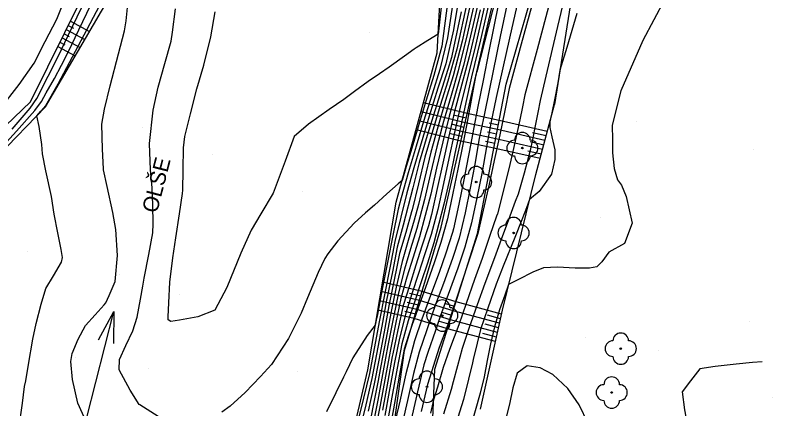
# Model space of a CAD drawing. Extents: x -448957 to -448612, y -1107690 to -1107245.
# Drawn here: x -448666.49 to -448618.03, y -1107372.46 to -1107347.3 of the extents above; entities that cross this region are included whole.
import ezdxf

# ---------------------------------------------------------------- set-up
doc = ezdxf.new("R2010")
doc.units = 0
for name, color, linetype in [('22', 7, 'Continuous'), ('Default', 7, 'Continuous'), ('Vrstva 1', 7, 'Continuous'), ('Vrstva 14', 7, 'Continuous'), ('Vrstva 15', 7, 'Continuous'), ('Vrstva 16', 7, 'Continuous'), ('Vrstva 17', 7, 'Continuous'), ('Vrstva 22', 7, 'Continuous'), ('Vrstva 45', 7, 'Continuous')]:
    doc.layers.add(name, color=color, linetype=linetype)

# ---------------------------------------------------------------- blocks, each defined once
blk = doc.blocks.new('POINT_DISPLAY')
at = {"layer": 'Default'}
blk.add_line((0, 0), (0, 0), dxfattribs=at)
blk = doc.blocks.new('STROM$5')
at = {"layer": '22'}
blk.add_circle((0, 0), 0.5, dxfattribs=at)
for centre, start, end in [((0, 5), 0, 180), ((-5, 0), 90, 270), ((5, 0), 270, 90), ((0, -5), 180, 0)]:
    blk.add_arc(centre, 5, start, end, dxfattribs=at)
blk = doc.blocks.new('TOK')
at = {"layer": 'Default'}
for p, q in [((-5, 50), (0, 70)), ((0, 0), (0, 70)), ((0, 70), (5, 50))]:
    blk.add_line(p, q, dxfattribs=at)

msp = doc.modelspace()

# ---------------------------------------------------------------- linework, layer by layer
at = {"layer": 'Vrstva 14'}
for p, q in [((-448639.5, -1107349.716), (-448638.523, -1107332.119)), ((-448632.378, -1107333.085), (-448636.968, -1107350.917)), ((-448635.081, -1107351.7), (-448629.722, -1107333.044)), ((-448628.814, -1107332.973), (-448631.997, -1107353.013)), ((-448665.508, -1107352.833), (-448661.274, -1107344.294)), ((-448664.543, -1107353.162), (-448659.693, -1107344.838)), ((-448642.118, -1107359.249), (-448639.5, -1107349.716)), ((-448639.238, -1107360.851), (-448636.968, -1107350.917)), ((-448636.914, -1107361.247), (-448635.081, -1107351.7)), ((-448673.407, -1107360.41), (-448665.508, -1107352.833)), ((-448672.108, -1107360.875), (-448664.543, -1107353.162)), ((-448633.189, -1107357.486), (-448631.997, -1107353.013)), ((-448635.327, -1107366.145), (-448633.189, -1107357.486)), ((-448643.941, -1107369.964), (-448642.118, -1107359.249)), ((-448641.584, -1107368.733), (-448639.238, -1107360.851)), ((-448639.643, -1107369.918), (-448636.914, -1107361.247)), ((-448636.736, -1107372.468), (-448635.327, -1107366.145)), ((-448643.143, -1107379.65), (-448641.584, -1107368.733)), ((-448646.084, -1107379.123), (-448643.941, -1107369.964)), ((-448640.133, -1107381.504), (-448639.643, -1107369.918))]:
    msp.add_line(p, q, dxfattribs=at)
at = {"layer": 'Vrstva 15'}
for p, q in [((-448662.953, -1107347.68), (-448661.732, -1107348.338)), ((-448663.22, -1107348.218), (-448662.034, -1107348.856)), ((-448663.086, -1107347.949), (-448662.748, -1107348.131)), ((-448663.486, -1107348.756), (-448662.337, -1107349.375)), ((-448663.353, -1107348.487), (-448663.024, -1107348.664)), ((-448663.753, -1107349.294), (-448662.639, -1107349.894)), ((-448663.62, -1107349.025), (-448663.301, -1107349.196)), ((-448637.58, -1107353.594), (-448640.372, -1107352.892)), ((-448637.713, -1107354.179), (-448640.531, -1107353.47)), ((-448637.646, -1107353.886), (-448638.444, -1107353.686)), ((-448635.527, -1107354.025), (-448637.58, -1107353.594)), ((-448637.847, -1107354.764), (-448640.69, -1107354.049)), ((-448635.641, -1107354.614), (-448637.713, -1107354.179)), ((-448632.454, -1107354.729), (-448635.527, -1107354.025)), ((-448637.981, -1107355.349), (-448640.849, -1107354.628)), ((-448637.78, -1107354.471), (-448638.585, -1107354.269)), ((-448635.584, -1107354.32), (-448636.17, -1107354.196)), ((-448632.609, -1107355.309), (-448635.641, -1107354.615)), ((-448637.914, -1107355.056), (-448638.726, -1107354.852)), ((-448635.754, -1107355.204), (-448637.847, -1107354.764)), ((-448635.697, -1107354.909), (-448636.289, -1107354.785)), ((-448632.531, -1107355.019), (-448633.41, -1107354.818)), ((-448635.867, -1107355.793), (-448637.981, -1107355.349)), ((-448635.81, -1107355.498), (-448636.408, -1107355.373)), ((-448632.763, -1107355.889), (-448635.754, -1107355.204)), ((-448632.686, -1107355.599), (-448633.552, -1107355.4)), ((-448632.918, -1107356.469), (-448635.867, -1107355.794)), ((-448632.841, -1107356.179), (-448633.695, -1107355.983)), ((-448640.461, -1107364.959), (-448642.989, -1107364.37)), ((-448640.632, -1107365.536), (-448643.09, -1107364.963)), ((-448640.547, -1107365.248), (-448641.269, -1107365.079)), ((-448638.291, -1107365.624), (-448640.461, -1107364.959)), ((-448640.804, -1107366.112), (-448643.191, -1107365.555)), ((-448640.718, -1107365.824), (-448641.42, -1107365.66)), ((-448638.472, -1107366.196), (-448640.632, -1107365.535)), ((-448638.382, -1107365.91), (-448639.001, -1107365.72)), ((-448635.385, -1107366.403), (-448638.291, -1107365.624)), ((-448640.975, -1107366.688), (-448643.292, -1107366.148)), ((-448640.89, -1107366.4), (-448641.572, -1107366.241)), ((-448638.652, -1107366.768), (-448640.803, -1107366.11)), ((-448638.562, -1107366.482), (-448639.179, -1107366.293)), ((-448635.515, -1107366.99), (-448638.472, -1107366.196)), ((-448638.832, -1107367.341), (-448640.974, -1107366.685)), ((-448635.646, -1107367.576), (-448638.652, -1107366.769)), ((-448635.45, -1107366.697), (-448636.28, -1107366.474)), ((-448638.742, -1107367.054), (-448639.356, -1107366.866)), ((-448635.581, -1107367.283), (-448636.425, -1107367.056)), ((-448635.776, -1107368.162), (-448638.832, -1107367.342)), ((-448635.711, -1107367.869), (-448636.57, -1107367.638))]:
    msp.add_line(p, q, dxfattribs=at)
at = {"layer": 'Vrstva 16'}
for points in [[(-448634.838, -1107345.644), (-448635.47, -1107348.671), (-448636.153, -1107352.014), (-448636.495, -1107353.684), (-448636.805, -1107355.19), (-448637.098, -1107356.811), (-448637.378, -1107358.347), (-448637.703, -1107359.935), (-448638.09, -1107361.54), (-448638.524, -1107362.847), (-448639.095, -1107364.449), (-448639.602, -1107365.79), (-448640.16, -1107367.4), (-448640.639, -1107368.83), (-448641.002, -1107370.2), (-448641.402, -1107371.934), (-448641.692, -1107373.219)], [(-448667.925, -1107356.375), (-448666.407, -1107354.708), (-448665.235, -1107353.392), (-448664.81, -1107352.82), (-448664.498, -1107352.256), (-448663.978, -1107351.336), (-448663.512, -1107350.501), (-448663.09, -1107349.674), (-448662.412, -1107348.242), (-448661.639, -1107346.632)], [(-448637.968, -1107347.084), (-448638.444, -1107349.382), (-448638.576, -1107349.995), (-448638.808, -1107350.765), (-448639.306, -1107352.324), (-448639.653, -1107353.414), (-448640.127, -1107354.985), (-448640.648, -1107356.709), (-448641.058, -1107358.341), (-448641.677, -1107360.71), (-448642.049, -1107362.132), (-448642.365, -1107363.706), (-448642.728, -1107365.523), (-448643.039, -1107367.169), (-448643.38, -1107368.974), (-448643.679, -1107370.525), (-448644.056, -1107372.192), (-448644.417, -1107373.675)], [(-448636.757, -1107346.965), (-448637.451, -1107349.97), (-448638.385, -1107353.454), (-448638.765, -1107355.113), (-448639.146, -1107356.767), (-448639.496, -1107358.378), (-448639.863, -1107360.04), (-448640.055, -1107360.77), (-448640.473, -1107362.068), (-448640.869, -1107363.283), (-448641.278, -1107364.587), (-448641.672, -1107365.844), (-448642.022, -1107367.406), (-448642.34, -1107368.936), (-448642.378, -1107369.121), (-448642.659, -1107370.692), (-448642.997, -1107372.552)], [(-448630.567, -1107347.19), (-448631.215, -1107349.365), (-448631.647, -1107350.807), (-448631.789, -1107351.62), (-448631.995, -1107352.71), (-448632.173, -1107353.546), (-448632.288, -1107354.106), (-448632.288, -1107354.277), (-448632.286, -1107354.488), (-448632.167, -1107355.066), (-448631.975, -1107355.895), (-448631.967, -1107356.531), (-448632.191, -1107357.455), (-448632.968, -1107358.56), (-448633.585, -1107359.089), (-448633.783, -1107359.608), (-448634.079, -1107360.389), (-448634.538, -1107361.516), (-448635.274, -1107363.342), (-448635.723, -1107364.5), (-448636.263, -1107366.033), (-448636.735, -1107367.397), (-448636.944, -1107368.267), (-448637.194, -1107369.308), (-448637.243, -1107369.512), (-448637.485, -1107370.559), (-448637.809, -1107371.857), (-448638.31, -1107373.42)]]:
    msp.add_lwpolyline(points, dxfattribs=at)
at = {"layer": 'Vrstva 17'}
for points in [[(-448667.516, -1107353.349), (-448666.237, -1107351.73), (-448665.263, -1107350.375), (-448664.557, -1107348.977), (-448663.821, -1107347.557), (-448663.111, -1107345.787), (-448662.585, -1107344.345), (-448662.505, -1107344.114), (-448662.472, -1107343.99), (-448662.32, -1107343.423), (-448662.081, -1107342.57), (-448661.948, -1107342.013), (-448662.027, -1107339.815), (-448662.213, -1107337.02), (-448662.425, -1107335.598), (-448662.903, -1107332.976), (-448663.381, -1107328.546), (-448663.491, -1107325.878), (-448663.429, -1107325.418), (-448662.646, -1107323.333), (-448661.288, -1107320.368), (-448660.143, -1107318.417), (-448659.03, -1107316.692)], [(-448636.52, -1107344.916), (-448637.202, -1107347.896), (-448637.81, -1107350.513), (-448637.828, -1107350.579), (-448638.283, -1107352.159), (-448638.741, -1107353.75), (-448639.135, -1107355.395), (-448639.535, -1107357.086), (-448639.904, -1107358.747), (-448640.621, -1107361.455), (-448641.037, -1107362.755), (-448641.43, -1107364.039), (-448641.829, -1107365.408), (-448642.147, -1107366.943), (-448642.513, -1107368.762), (-448642.803, -1107370.362), (-448643.149, -1107372.226), (-448643.435, -1107373.732)], [(-448637.958, -1107345.243), (-448638.463, -1107348.227), (-448638.95, -1107350.404), (-448639.446, -1107351.964), (-448640.008, -1107353.756), (-448640.997, -1107357.046), (-448641.428, -1107358.657), (-448641.83, -1107360.201), (-448642.196, -1107361.759), (-448642.511, -1107363.349), (-448642.869, -1107365.163), (-448643.181, -1107366.794), (-448643.524, -1107368.6), (-448643.832, -1107370.199), (-448644.213, -1107371.781), (-448644.576, -1107373.236)], [(-448636.875, -1107345.428), (-448637.55, -1107348.442), (-448638.145, -1107350.848), (-448638.611, -1107352.423), (-448639.101, -1107354.099), (-448639.52, -1107355.722), (-448639.924, -1107357.42), (-448640.302, -1107359.076), (-448640.792, -1107360.925), (-448641.195, -1107362.232), (-448641.587, -1107363.539), (-448641.976, -1107365.046), (-448642.294, -1107366.591), (-448642.649, -1107368.403), (-448642.947, -1107370.032), (-448643.301, -1107371.9), (-448643.588, -1107373.387)], [(-448635.679, -1107345.337), (-448636.376, -1107348.342), (-448636.976, -1107350.925), (-448637.008, -1107351.079), (-448637.038, -1107351.222), (-448637.273, -1107352.487), (-448637.56, -1107354.014), (-448637.845, -1107355.464), (-448638.173, -1107357.14), (-448638.497, -1107358.676), (-448638.846, -1107360.311), (-448639.269, -1107361.829), (-448639.697, -1107363.136), (-448640.24, -1107364.694), (-448640.704, -1107365.996), (-448640.908, -1107366.556), (-448641.067, -1107366.997), (-448641.331, -1107367.771), (-448641.617, -1107368.653), (-448641.899, -1107370.235), (-448642.229, -1107372.091), (-448642.511, -1107373.643)], [(-448638.39, -1107345.799), (-448638.832, -1107348.756), (-448639.335, -1107350.779), (-448639.824, -1107352.343), (-448640.363, -1107354.098), (-448640.833, -1107355.671), (-448641.346, -1107357.383), (-448641.797, -1107358.974), (-448641.984, -1107359.692), (-448642.342, -1107361.385), (-448642.656, -1107362.991), (-448643.01, -1107364.803), (-448643.323, -1107366.419), (-448643.393, -1107366.785), (-448643.456, -1107367.116), (-448643.983, -1107367.765), (-448644.883, -1107369.202), (-448645.321, -1107370.102), (-448645.489, -1107370.427), (-448645.98, -1107371.441), (-448646.579, -1107372.65)], [(-448637.229, -1107345.939), (-448637.892, -1107348.96), (-448638.481, -1107351.182), (-448638.957, -1107352.752), (-448639.46, -1107354.449), (-448639.904, -1107356.049), (-448640.312, -1107357.753), (-448640.699, -1107359.404), (-448640.962, -1107360.395), (-448641.353, -1107361.708), (-448641.743, -1107363.038), (-448642.124, -1107364.685), (-448642.441, -1107366.238), (-448642.784, -1107368.044), (-448643.091, -1107369.701), (-448643.273, -1107370.651), (-448643.561, -1107372.128), (-448643.743, -1107373.014)], [(-448636.039, -1107345.88), (-448636.735, -1107348.885), (-448637.303, -1107351.234), (-448637.675, -1107352.885), (-448638.01, -1107354.471), (-448638.366, -1107356.138), (-448638.698, -1107357.718), (-448639.066, -1107359.379), (-448639.713, -1107361.848), (-448640.125, -1107363.15), (-448640.523, -1107364.345), (-448640.948, -1107365.64), (-448641.346, -1107366.837), (-448641.765, -1107368.299), (-448642.059, -1107369.864), (-448642.393, -1107371.722), (-448642.676, -1107373.268)], [(-448634.184, -1107345.747), (-448634.881, -1107348.762), (-448635.722, -1107352.552), (-448636.056, -1107354.191), (-448636.333, -1107355.719), (-448636.627, -1107357.312), (-448636.968, -1107358.981), (-448637.295, -1107360.569), (-448637.737, -1107362.118), (-448638.179, -1107363.46), (-448638.788, -1107365.152), (-448639.305, -1107366.559), (-448639.61, -1107367.441), (-448640.1, -1107368.865), (-448640.351, -1107369.644), (-448640.761, -1107371.372), (-448641.442, -1107374.363)], [(-448631.248, -1107345.684), (-448631.811, -1107348.029), (-448632.55, -1107351.204), (-448632.905, -1107352.753), (-448633.061, -1107353.517), (-448633.225, -1107354.368), (-448633.372, -1107355.136), (-448633.548, -1107355.949), (-448633.939, -1107357.386), (-448634.326, -1107358.728), (-448634.503, -1107359.197), (-448634.944, -1107360.379), (-448635.4, -1107361.633), (-448635.841, -1107362.816), (-448636.455, -1107364.458), (-448636.938, -1107365.813), (-448637.475, -1107367.33), (-448637.899, -1107368.605), (-448638.193, -1107369.711), (-448638.466, -1107370.731), (-448638.607, -1107371.223), (-448639.084, -1107372.807)], [(-448661.876, -1107373.405), (-448662.481, -1107372.103), (-448662.814, -1107370.593), (-448662.921, -1107369.437), (-448662.85, -1107368.918), (-448662.462, -1107368.002), (-448661.987, -1107367.139), (-448661.372, -1107366.454), (-448660.799, -1107365.817), (-448660.694, -1107365.681), (-448660.483, -1107365.222), (-448660.086, -1107364.325), (-448659.932, -1107362.655), (-448660.045, -1107360.998), (-448660.248, -1107359.91), (-448660.603, -1107358.249), (-448660.829, -1107357.186), (-448660.841, -1107357.127), (-448660.892, -1107355.855), (-448660.953, -1107354.263), (-448660.782, -1107353.303), (-448660.403, -1107351.825), (-448659.883, -1107349.779), (-448659.483, -1107348.305), (-448659.377, -1107347.66), (-448659.245, -1107346.147)], [(-448639.174, -1107346.198), (-448639.433, -1107348.504), (-448640.099, -1107348.916), (-448640.843, -1107349.383), (-448640.966, -1107349.472), (-448641.584, -1107349.92), (-448642.56, -1107350.617), (-448643.178, -1107351.058), (-448643.907, -1107351.544), (-448644.791, -1107352.168), (-448645.458, -1107352.699), (-448646.397, -1107353.333), (-448647.717, -1107354.268), (-448648.648, -1107355.045), (-448649.221, -1107356.628), (-448649.983, -1107358.682), (-448650.776, -1107359.991), (-448651.384, -1107361.043), (-448652.048, -1107362.512), (-448652.954, -1107364.701), (-448653.724, -1107366.147), (-448654.8, -1107366.571), (-448655.981, -1107366.799), (-448656.535, -1107366.871), (-448656.708, -1107366.769), (-448656.71, -1107366.572), (-448656.668, -1107365.691), (-448656.59, -1107364.353), (-448656.397, -1107362.81), (-448656.2, -1107361.521), (-448655.972, -1107359.988), (-448655.774, -1107358.699), (-448655.772, -1107358.475), (-448655.746, -1107357.191), (-448655.722, -1107355.767), (-448655.633, -1107355.052), (-448655.281, -1107353.596), (-448654.877, -1107352.007), (-448654.415, -1107350.501), (-448653.967, -1107348.682), (-448653.7, -1107347.089)], [(-448638.822, -1107346.355), (-448639.2, -1107349.285), (-448639.72, -1107351.155), (-448640.202, -1107352.722), (-448640.718, -1107354.44), (-448641.186, -1107356.014), (-448641.473, -1107356.974), (-448641.737, -1107357.86), (-448642.002, -1107358.085), (-448642.712, -1107358.72), (-448643.508, -1107359.431), (-448644.086, -1107359.942), (-448644.807, -1107360.59), (-448645.843, -1107361.716), (-448646.498, -1107362.543), (-448646.68, -1107362.849), (-448647.104, -1107363.754), (-448647.801, -1107365.356), (-448648.196, -1107366.34), (-448648.3, -1107366.563), (-448649.005, -1107367.961), (-448650.083, -1107369.633), (-448650.791, -1107370.387), (-448651.777, -1107371.416), (-448652.742, -1107372.289), (-448653.277, -1107372.661)], [(-448636.398, -1107346.422), (-448637.093, -1107349.428), (-448637.629, -1107351.544), (-448638.03, -1107353.17), (-448638.387, -1107354.792), (-448638.756, -1107356.453), (-448639.097, -1107358.048), (-448639.465, -1107359.71), (-448639.884, -1107361.309), (-448640.299, -1107362.609), (-448640.696, -1107363.814), (-448641.113, -1107365.114), (-448641.509, -1107366.341), (-448641.913, -1107367.945), (-448642.219, -1107369.492), (-448642.558, -1107371.353), (-448642.841, -1107372.893)], [(-448633.28, -1107346.036), (-448634.134, -1107349.162), (-448634.893, -1107351.976), (-448635.18, -1107353.386), (-448635.498, -1107354.941), (-448635.851, -1107356.58), (-448636.183, -1107358.089), (-448636.56, -1107359.753), (-448636.897, -1107361.247), (-448637.107, -1107361.884), (-448637.307, -1107362.496), (-448637.572, -1107363.313), (-448637.848, -1107364.163), (-448638.326, -1107365.595), (-448638.84, -1107367.136), (-448639.373, -1107368.533), (-448640.124, -1107370.894), (-448640.528, -1107372.626)], [(-448632.269, -1107346.365), (-448633.107, -1107349.497), (-448633.882, -1107352.393), (-448634.041, -1107353.155), (-448634.213, -1107353.983), (-448634.504, -1107355.356), (-448634.845, -1107356.838), (-448635.284, -1107358.563), (-448635.643, -1107359.991), (-448635.7, -1107360.153), (-448636.126, -1107361.382), (-448636.624, -1107362.841), (-448637.107, -1107364.201), (-448637.644, -1107365.718), (-448638.122, -1107367.094), (-448638.714, -1107368.659), (-448639.124, -1107369.809), (-448639.487, -1107371.072), (-448639.726, -1107371.88), (-448639.914, -1107372.739)], [(-448624.946, -1107346.261), (-448626.341, -1107348.916), (-448627.747, -1107352.145), (-448628.309, -1107354.339), (-448628.275, -1107355.269), (-448628.277, -1107356.087), (-448628.171, -1107357.095), (-448627.967, -1107357.822), (-448627.705, -1107358.164), (-448627.418, -1107358.885), (-448627.025, -1107360.599), (-448627.509, -1107361.898), (-448628.517, -1107362.443), (-448628.968, -1107363.058), (-448629.294, -1107363.374), (-448629.752, -1107363.458), (-448630.677, -1107363.472), (-448631.806, -1107363.412), (-448632.699, -1107363.443), (-448633.382, -1107363.726), (-448634.302, -1107364.194), (-448634.926, -1107364.519), (-448635.175, -1107365.183), (-448635.52, -1107366.122), (-448635.821, -1107367.225), (-448636.087, -1107368.305), (-448636.301, -1107369.377), (-448636.502, -1107370.402), (-448636.745, -1107371.449), (-448637.397, -1107373.709)], [(-448666.682, -1107354.576), (-448665.533, -1107353.252), (-448665.104, -1107352.622), (-448664.378, -1107351.206), (-448663.747, -1107349.986), (-448663.068, -1107348.554), (-448662.25, -1107346.826)], [(-448666.249, -1107373.706), (-448666.024, -1107372.092), (-448665.88, -1107371.036), (-448665.807, -1107370.677), (-448665.638, -1107369.625), (-448665.353, -1107368.014), (-448665.137, -1107366.997), (-448664.828, -1107365.768), (-448664.525, -1107364.776), (-448664.032, -1107363.951), (-448663.514, -1107363.082), (-448663.46, -1107362.786), (-448663.549, -1107362.28), (-448663.767, -1107361.209), (-448663.989, -1107360.023), (-448664.171, -1107358.891), (-448664.514, -1107357.24), (-448664.746, -1107356.162), (-448664.774, -1107355.574), (-448664.946, -1107354.417), (-448665.101, -1107353.73), (-448664.835, -1107353.442), (-448664.525, -1107353.074), (-448663.745, -1107351.677), (-448662.818, -1107349.966), (-448662.067, -1107348.559), (-448661.083, -1107346.696)], [(-448657.338, -1107372.938), (-448658.516, -1107372.211), (-448658.556, -1107372.173), (-448659.127, -1107371.262), (-448659.827, -1107369.961), (-448659.823, -1107369.295), (-448659.409, -1107368.405), (-448658.962, -1107367.464), (-448658.686, -1107366.607), (-448658.474, -1107365.454), (-448658.319, -1107364.61), (-448658.228, -1107364.101), (-448657.938, -1107362.589), (-448657.674, -1107361.215), (-448657.651, -1107360.64), (-448657.674, -1107359.419), (-448657.732, -1107358.326), (-448657.821, -1107357.19), (-448657.897, -1107355.503), (-448657.653, -1107353.371), (-448657.341, -1107351.9), (-448656.923, -1107350.388), (-448656.516, -1107348.953), (-448656.419, -1107348.395), (-448656.237, -1107346.894)], [(-448637.584, -1107346.451), (-448638.234, -1107349.477), (-448638.816, -1107351.516), (-448639.304, -1107353.08), (-448639.82, -1107354.799), (-448640.288, -1107356.376), (-448640.701, -1107358.086), (-448641.097, -1107359.732), (-448641.132, -1107359.865), (-448641.511, -1107361.185), (-448641.9, -1107362.538), (-448642.08, -1107363.38), (-448642.397, -1107364.941), (-448642.586, -1107365.883), (-448642.897, -1107367.543), (-448643.235, -1107369.347), (-448643.527, -1107370.851), (-448643.9, -1107372.603)], [(-448635.579, -1107346.555), (-448636.193, -1107349.59), (-448636.563, -1107351.464), (-448636.89, -1107353.141), (-448637.175, -1107354.593), (-448637.35, -1107355.49), (-448637.632, -1107356.933), (-448637.782, -1107357.708), (-448638.118, -1107359.368), (-448638.443, -1107360.955), (-448638.519, -1107361.196), (-448638.953, -1107362.502), (-448639.368, -1107363.744), (-448639.852, -1107365.042), (-448640.48, -1107366.735), (-448640.953, -1107368.113), (-448641.509, -1107370.221), (-448641.895, -1107371.964), (-448642.157, -1107373.135)], [(-448618.724, -1107369.461), (-448619.341, -1107369.494), (-448620.378, -1107369.595), (-448621.723, -1107369.753), (-448622.71, -1107369.91), (-448623.299, -1107370.667), (-448623.83, -1107371.366), (-448623.683, -1107372.514), (-448623.3, -1107374.514), (-448622.956, -1107375.716), (-448622.783, -1107376.264), (-448622.263, -1107378.095), (-448621.717, -1107380.072), (-448621.628, -1107380.425)], [(-448629.849, -1107373.389), (-448630.416, -1107372.198), (-448631.151, -1107371.164), (-448632.093, -1107370.253), (-448632.903, -1107369.837), (-448633.74, -1107369.708), (-448634.377, -1107370.184), (-448634.651, -1107371.113), (-448634.881, -1107372.167), (-448635.21, -1107373.508)]]:
    msp.add_lwpolyline(points, dxfattribs=at)

# ---------------------------------------------------------------- block references
at = {"layer": 'Vrstva 1', "xscale": 0.1, "yscale": 0.10000000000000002}
for p in [(-448639.5, -1107349.716), (-448636.968, -1107350.917), (-448635.081, -1107351.7), (-448665.508, -1107352.833), (-448664.543, -1107353.162), (-448631.997, -1107353.013), (-448633.189, -1107357.486), (-448642.118, -1107359.249), (-448639.238, -1107360.851), (-448636.914, -1107361.247), (-448635.327, -1107366.145), (-448641.584, -1107368.733), (-448643.941, -1107369.964), (-448639.643, -1107369.918)]:
    msp.add_blockref('POINT_DISPLAY', p, dxfattribs=at)
at = {"layer": 'Vrstva 14', "xscale": 0.1, "yscale": 0.10000000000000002}
for p in [(-448643.842, -1107348.383), (-448626.779, -1107354.122), (-448658.343, -1107354.476), (-448619.287, -1107355.91), (-448653.865, -1107356.173), (-448648.123, -1107358.565), (-448629.027, -1107360.2), (-448665.721, -1107362.385), (-448659.804, -1107363.875), (-448655.987, -1107365.122), (-448619.511, -1107366.847), (-448630.009, -1107367.881), (-448625.347, -1107368.723), (-448662.599, -1107369.17), (-448657.942, -1107369.85), (-448648.445, -1107370.052), (-448618.031, -1107371.761)]:
    msp.add_blockref('POINT_DISPLAY', p, dxfattribs=at)
at = {"layer": 'Vrstva 22', "xscale": 0.1, "yscale": 0.10000000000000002}
for p in [(-448634.05, -1107355.792), (-448637.003, -1107357.965), (-448634.609, -1107361.22), (-448639.17, -1107366.496), (-448627.758, -1107368.611), (-448640.152, -1107371.048), (-448628.337, -1107371.415)]:
    msp.add_blockref('STROM$5', p, dxfattribs=at)
at = {"layer": 'Vrstva 45', "xscale": 0.09999999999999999, "yscale": 0.10000000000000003, "rotation": -14.355691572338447}
msp.add_blockref('TOK', (-448661.911, -1107373.01), dxfattribs=at)

# ---------------------------------------------------------------- texts
at = {"layer": 'Vrstva 45'}
msp.add_text('OLŠE', height=1, rotation=75.591, dxfattribs=at).set_placement((-448657.42, -1107359.998))

doc.saveas('drawing.dxf')
